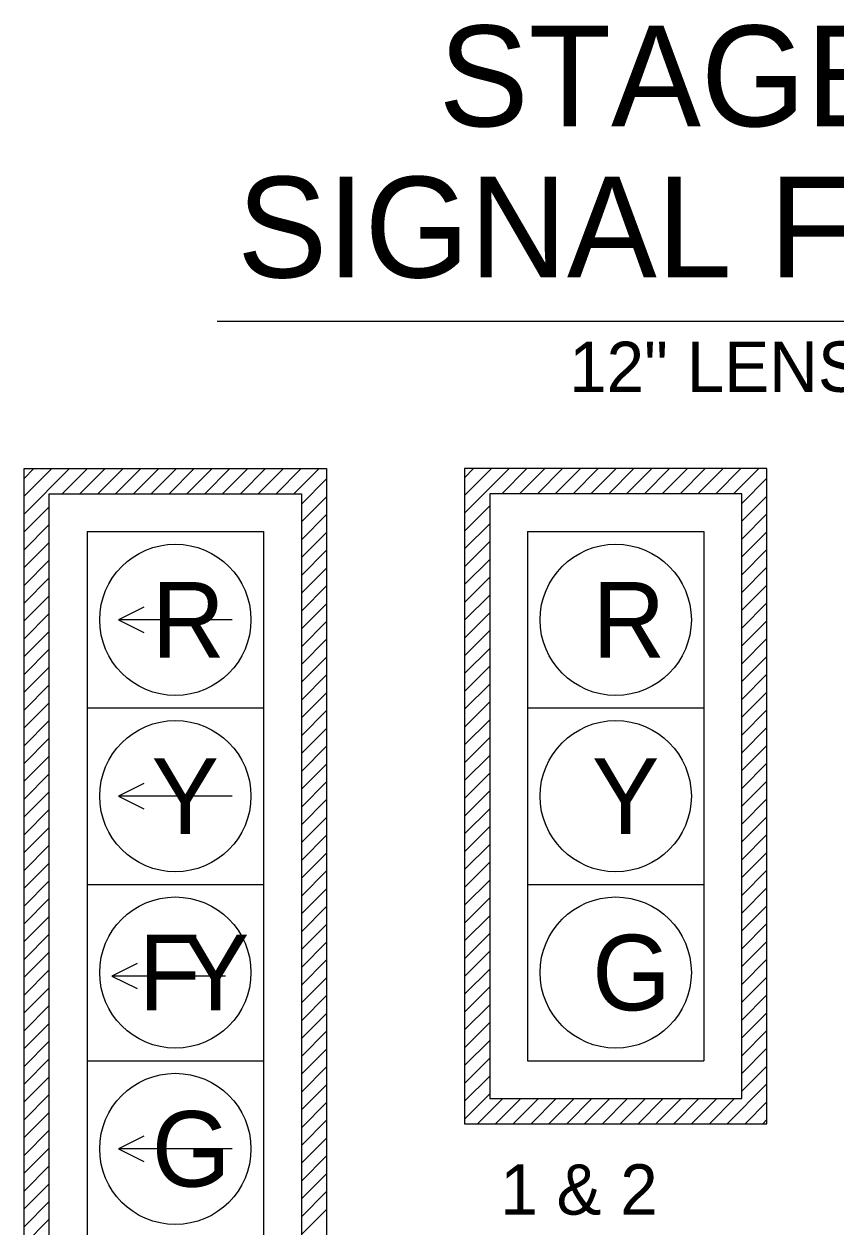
# Model space of a CAD drawing. Extents: x -218554 to 420030, y -565899 to -483460.
# Drawn here: x 419080.6 to 419145, y -565376.2 to -565280.7 of the extents above; entities that cross this region are included whole.
import ezdxf

# ---------------------------------------------------------------- set-up
doc = ezdxf.new("R2010")
doc.units = 0
doc.layers.add('T_Drafting', color=7, linetype='Continuous')
doc.layers.add('T_Notes', color=7, linetype='Continuous')

msp = doc.modelspace()

# ---------------------------------------------------------------- linework, layer by layer
at = {"layer": 'T_Drafting'}
for p, q in [((419080.555, -565381.971), (419080.555, -565315.971)), ((419080.555, -565315.971), (419104.555, -565315.971)), ((419080.555, -565319.578), (419084.163, -565315.971)), ((419080.555, -565318.163), (419082.748, -565315.971)), ((419080.555, -565316.749), (419081.334, -565315.971)), ((419083.577, -565317.971), (419085.577, -565315.971)), ((419084.991, -565317.971), (419086.991, -565315.971)), ((419086.405, -565317.971), (419088.405, -565315.971)), ((419087.819, -565317.971), (419089.819, -565315.971)), ((419089.234, -565317.971), (419091.234, -565315.971)), ((419090.648, -565317.971), (419092.648, -565315.971)), ((419092.062, -565317.971), (419094.062, -565315.971)), ((419093.476, -565317.971), (419095.476, -565315.971)), ((419094.89, -565317.971), (419096.89, -565315.971)), ((419096.305, -565317.971), (419098.305, -565315.971)), ((419097.719, -565317.971), (419099.719, -565315.971)), ((419099.133, -565317.971), (419101.133, -565315.971)), ((419100.547, -565317.971), (419102.547, -565315.971)), ((419101.962, -565317.971), (419103.962, -565315.971)), ((419104.555, -565315.971), (419104.555, -565381.971)), ((419139.493, -565315.971), (419115.493, -565315.971)), ((419115.493, -565315.971), (419115.493, -565367.971)), ((419115.493, -565319.517), (419119.04, -565315.971)), ((419115.493, -565318.103), (419117.626, -565315.971)), ((419115.493, -565316.689), (419116.212, -565315.971)), ((419118.454, -565317.971), (419120.454, -565315.971)), ((419119.869, -565317.971), (419121.869, -565315.971)), ((419121.283, -565317.971), (419123.283, -565315.971)), ((419122.697, -565317.971), (419124.697, -565315.971)), ((419124.111, -565317.971), (419126.111, -565315.971)), ((419125.525, -565317.971), (419127.525, -565315.971)), ((419126.94, -565317.971), (419128.94, -565315.971)), ((419128.354, -565317.971), (419130.354, -565315.971)), ((419129.768, -565317.971), (419131.768, -565315.971)), ((419131.182, -565317.971), (419133.182, -565315.971)), ((419132.596, -565317.971), (419134.596, -565315.971)), ((419134.011, -565317.971), (419136.011, -565315.971)), ((419135.425, -565317.971), (419137.425, -565315.971)), ((419136.839, -565317.971), (419138.839, -565315.971)), ((419139.493, -565367.971), (419139.493, -565315.971)), ((419102.555, -565318.791), (419104.555, -565316.791)), ((419137.493, -565318.731), (419139.493, -565316.731)), ((419102.555, -565320.205), (419104.555, -565318.205)), ((419137.493, -565320.145), (419139.493, -565318.145)), ((419080.555, -565320.992), (419082.555, -565318.992)), ((419102.555, -565321.619), (419104.555, -565319.619)), ((419115.493, -565320.932), (419117.493, -565318.932)), ((419137.493, -565321.559), (419139.493, -565319.559)), ((419080.555, -565322.406), (419082.555, -565320.406)), ((419115.493, -565322.346), (419117.493, -565320.346)), ((419085.555, -565320.971), (419099.555, -565320.971)), ((419085.555, -565320.971), (419085.555, -565334.971)), ((419099.555, -565320.971), (419099.555, -565334.971)), ((419102.555, -565323.033), (419104.555, -565321.033)), ((419115.493, -565323.76), (419117.493, -565321.76)), ((419120.493, -565320.971), (419134.493, -565320.971)), ((419120.493, -565320.971), (419120.493, -565334.971)), ((419134.493, -565320.971), (419134.493, -565334.971)), ((419137.493, -565322.973), (419139.493, -565320.973)), ((419080.555, -565323.82), (419082.555, -565321.82)), ((419102.555, -565324.448), (419104.555, -565322.448)), ((419137.493, -565324.387), (419139.493, -565322.387)), ((419080.555, -565325.234), (419082.555, -565323.234)), ((419115.493, -565325.174), (419117.493, -565323.174)), ((419080.555, -565326.649), (419082.555, -565324.649)), ((419102.555, -565325.862), (419104.555, -565323.862)), ((419115.493, -565326.588), (419117.493, -565324.588)), ((419137.493, -565325.802), (419139.493, -565323.802)), ((419102.555, -565327.276), (419104.555, -565325.276)), ((419137.493, -565327.216), (419139.493, -565325.216)), ((419080.555, -565328.063), (419082.555, -565326.063)), ((419115.493, -565328.003), (419117.493, -565326.003)), ((419080.555, -565329.477), (419082.555, -565327.477)), ((419102.555, -565328.69), (419104.555, -565326.69)), ((419115.493, -565329.417), (419117.493, -565327.417)), ((419137.493, -565328.63), (419139.493, -565326.63)), ((419097.055, -565327.971), (419088.055, -565327.971)), ((419102.555, -565330.105), (419104.555, -565328.105)), ((419137.493, -565330.044), (419139.493, -565328.044)), ((419080.555, -565330.891), (419082.555, -565328.891)), ((419115.493, -565330.831), (419117.493, -565328.831)), ((419080.555, -565332.306), (419082.555, -565330.306)), ((419102.555, -565331.519), (419104.555, -565329.519)), ((419115.493, -565332.245), (419117.493, -565330.245)), ((419137.493, -565331.458), (419139.493, -565329.458)), ((419102.555, -565332.933), (419104.555, -565330.933)), ((419137.493, -565332.873), (419139.493, -565330.873)), ((419080.555, -565333.72), (419082.555, -565331.72)), ((419115.493, -565333.659), (419117.493, -565331.659)), ((419137.493, -565334.287), (419139.493, -565332.287)), ((419080.555, -565335.134), (419082.555, -565333.134)), ((419102.555, -565334.347), (419104.555, -565332.347)), ((419115.493, -565335.074), (419117.493, -565333.074)), ((419102.555, -565335.761), (419104.555, -565333.761)), ((419137.493, -565335.701), (419139.493, -565333.701)), ((419080.555, -565336.548), (419082.555, -565334.548)), ((419085.555, -565334.971), (419099.555, -565334.971)), ((419085.555, -565334.971), (419085.555, -565348.971)), ((419099.555, -565334.971), (419099.555, -565348.971)), ((419115.493, -565336.488), (419117.493, -565334.488)), ((419120.493, -565334.971), (419134.493, -565334.971)), ((419120.493, -565334.971), (419120.493, -565348.971)), ((419134.493, -565334.971), (419134.493, -565348.971)), ((419137.493, -565337.115), (419139.493, -565335.115)), ((419080.555, -565337.962), (419082.555, -565335.962)), ((419102.555, -565337.176), (419104.555, -565335.176)), ((419115.493, -565337.902), (419117.493, -565335.902)), ((419102.555, -565338.59), (419104.555, -565336.59)), ((419137.493, -565338.53), (419139.493, -565336.53)), ((419080.555, -565339.377), (419082.555, -565337.377)), ((419102.555, -565340.004), (419104.555, -565338.004)), ((419115.493, -565339.316), (419117.493, -565337.316)), ((419137.493, -565339.944), (419139.493, -565337.944)), ((419080.555, -565340.791), (419082.555, -565338.791)), ((419115.493, -565340.731), (419117.493, -565338.731)), ((419102.555, -565341.418), (419104.555, -565339.418)), ((419137.493, -565341.358), (419139.493, -565339.358)), ((419080.555, -565342.205), (419082.555, -565340.205)), ((419102.555, -565342.832), (419104.555, -565340.832)), ((419115.493, -565342.145), (419117.493, -565340.145)), ((419137.493, -565342.772), (419139.493, -565340.772)), ((419080.555, -565343.619), (419082.555, -565341.619)), ((419115.493, -565343.559), (419117.493, -565341.559)), ((419097.055, -565341.971), (419088.055, -565341.971)), ((419102.555, -565344.247), (419104.555, -565342.247)), ((419137.493, -565344.186), (419139.493, -565342.186)), ((419080.555, -565345.033), (419082.555, -565343.033)), ((419102.555, -565345.661), (419104.555, -565343.661)), ((419115.493, -565344.973), (419117.493, -565342.973)), ((419137.493, -565345.601), (419139.493, -565343.601)), ((419080.555, -565346.448), (419082.555, -565344.448)), ((419115.493, -565346.387), (419117.493, -565344.387)), ((419102.555, -565347.075), (419104.555, -565345.075)), ((419137.493, -565347.015), (419139.493, -565345.015)), ((419080.555, -565347.862), (419082.555, -565345.862)), ((419102.555, -565348.489), (419104.555, -565346.489)), ((419115.493, -565347.802), (419117.493, -565345.802)), ((419137.493, -565348.429), (419139.493, -565346.429)), ((419080.555, -565349.276), (419082.555, -565347.276)), ((419115.493, -565349.216), (419117.493, -565347.216)), ((419102.555, -565349.904), (419104.555, -565347.904)), ((419137.493, -565349.843), (419139.493, -565347.843)), ((419080.555, -565350.69), (419082.555, -565348.69)), ((419085.555, -565348.971), (419099.555, -565348.971)), ((419085.555, -565348.971), (419085.555, -565362.971)), ((419099.555, -565348.971), (419099.555, -565362.971)), ((419102.555, -565351.318), (419104.555, -565349.318)), ((419115.493, -565350.63), (419117.493, -565348.63)), ((419120.493, -565348.971), (419134.493, -565348.971)), ((419120.493, -565348.971), (419120.493, -565362.971)), ((419134.493, -565348.971), (419134.493, -565362.971)), ((419137.493, -565351.257), (419139.493, -565349.257)), ((419080.555, -565352.105), (419082.555, -565350.105)), ((419115.493, -565352.044), (419117.493, -565350.044)), ((419102.555, -565352.732), (419104.555, -565350.732)), ((419137.493, -565352.672), (419139.493, -565350.672)), ((419080.555, -565353.519), (419082.555, -565351.519)), ((419102.555, -565354.146), (419104.555, -565352.146)), ((419115.493, -565353.458), (419117.493, -565351.458)), ((419137.493, -565354.086), (419139.493, -565352.086)), ((419080.555, -565354.933), (419082.555, -565352.933)), ((419115.493, -565354.873), (419117.493, -565352.873)), ((419102.555, -565355.56), (419104.555, -565353.56)), ((419137.493, -565355.5), (419139.493, -565353.5)), ((419080.555, -565356.347), (419082.555, -565354.347)), ((419102.555, -565356.975), (419104.555, -565354.975)), ((419115.493, -565356.287), (419117.493, -565354.287)), ((419137.493, -565356.914), (419139.493, -565354.914)), ((419080.555, -565357.761), (419082.555, -565355.761)), ((419115.493, -565357.701), (419117.493, -565355.701)), ((419096.53, -565356.248), (419087.53, -565356.248)), ((419102.555, -565358.389), (419104.555, -565356.389)), ((419115.493, -565359.115), (419117.493, -565357.115)), ((419137.493, -565358.328), (419139.493, -565356.328)), ((419080.555, -565359.176), (419082.555, -565357.176)), ((419102.555, -565359.803), (419104.555, -565357.803)), ((419137.493, -565359.743), (419139.493, -565357.743)), ((419080.555, -565360.59), (419082.555, -565358.59)), ((419115.493, -565360.53), (419117.493, -565358.53)), ((419102.555, -565361.217), (419104.555, -565359.217)), ((419115.493, -565361.944), (419117.493, -565359.944)), ((419137.493, -565361.157), (419139.493, -565359.157)), ((419080.555, -565362.004), (419082.555, -565360.004)), ((419102.555, -565362.631), (419104.555, -565360.631)), ((419137.493, -565362.571), (419139.493, -565360.571)), ((419080.555, -565363.418), (419082.555, -565361.418)), ((419115.493, -565363.358), (419117.493, -565361.358)), ((419080.555, -565364.832), (419082.555, -565362.832)), ((419102.555, -565364.046), (419104.555, -565362.046)), ((419115.493, -565364.772), (419117.493, -565362.772)), ((419137.493, -565363.985), (419139.493, -565361.985)), ((419085.555, -565362.971), (419099.555, -565362.971)), ((419085.555, -565362.971), (419085.555, -565376.971)), ((419099.555, -565362.971), (419099.555, -565376.971)), ((419102.555, -565365.46), (419104.555, -565363.46)), ((419120.493, -565362.971), (419134.493, -565362.971)), ((419137.493, -565365.4), (419139.493, -565363.4)), ((419080.555, -565366.247), (419082.555, -565364.247)), ((419115.493, -565366.186), (419117.493, -565364.186)), ((419080.555, -565367.661), (419082.555, -565365.661)), ((419102.555, -565366.874), (419104.555, -565364.874)), ((419115.493, -565367.601), (419117.493, -565365.601)), ((419136.337, -565367.971), (419139.493, -565364.814)), ((419102.555, -565368.288), (419104.555, -565366.288)), ((419116.538, -565367.971), (419118.538, -565365.971)), ((419117.952, -565367.971), (419119.952, -565365.971)), ((419119.366, -565367.971), (419121.366, -565365.971)), ((419120.78, -565367.971), (419122.78, -565365.971)), ((419122.194, -565367.971), (419124.194, -565365.971)), ((419123.609, -565367.971), (419125.609, -565365.971)), ((419125.023, -565367.971), (419127.023, -565365.971)), ((419126.437, -565367.971), (419128.437, -565365.971)), ((419127.851, -565367.971), (419129.851, -565365.971)), ((419129.266, -565367.971), (419131.266, -565365.971)), ((419130.68, -565367.971), (419132.68, -565365.971)), ((419132.094, -565367.971), (419134.094, -565365.971)), ((419133.508, -565367.971), (419135.508, -565365.971)), ((419134.922, -565367.971), (419136.922, -565365.971)), ((419137.751, -565367.971), (419139.493, -565366.228)), ((419080.555, -565369.075), (419082.555, -565367.075)), ((419080.555, -565370.489), (419082.555, -565368.489)), ((419102.555, -565369.703), (419104.555, -565367.703)), ((419115.493, -565367.971), (419139.493, -565367.971)), ((419139.165, -565367.971), (419139.493, -565367.642)), ((419102.555, -565371.117), (419104.555, -565369.117)), ((419080.555, -565371.904), (419082.555, -565369.904)), ((419097.055, -565369.971), (419088.055, -565369.971)), ((419080.555, -565373.318), (419082.555, -565371.318)), ((419102.555, -565372.531), (419104.555, -565370.531)), ((419102.555, -565373.945), (419104.555, -565371.945)), ((419080.555, -565374.732), (419082.555, -565372.732)), ((419080.555, -565376.146), (419082.555, -565374.146)), ((419102.555, -565375.359), (419104.555, -565373.359)), ((419102.555, -565376.774), (419104.555, -565374.774)), ((419080.555, -565377.56), (419082.555, -565375.56))]:
    msp.add_line(p, q, dxfattribs=at)
for points in [[(419082.555, -565379.971), (419082.555, -565317.971), (419102.555, -565317.971), (419102.555, -565379.971)], [(419137.493, -565365.971), (419137.493, -565317.971), (419117.493, -565317.971), (419117.493, -565365.971)]]:
    msp.add_lwpolyline(points, close=True, dxfattribs=at)
for points in [[(419090.055, -565326.971), (419088.055, -565327.971), (419090.055, -565328.971)], [(419090.055, -565340.971), (419088.055, -565341.971), (419090.055, -565342.971)], [(419089.53, -565355.248), (419087.53, -565356.248), (419089.53, -565357.248)], [(419090.055, -565368.971), (419088.055, -565369.971), (419090.055, -565370.971)]]:
    msp.add_lwpolyline(points, dxfattribs=at)
for centre in [(419092.555, -565327.971), (419127.493, -565327.971), (419092.555, -565341.971), (419127.493, -565341.971), (419092.555, -565355.971), (419127.493, -565355.971), (419092.555, -565369.971)]:
    msp.add_circle(centre, 6, dxfattribs=at)
at = {"layer": 'T_Notes'}
msp.add_line((419095.87, -565304.265), (419194.055, -565304.265), dxfattribs=at)

# ---------------------------------------------------------------- texts
at = {"layer": 'T_Drafting'}
msp.add_text('12" LENSES', height=4, rotation=0.07203, dxfattribs=at).set_placement((419123.796, -565309.899))
for s, p in [('R', (419090.69, -565330.969)), ('R', (419125.628, -565330.969)), ('Y', (419090.667, -565344.969)), ('Y', (419125.604, -565344.969)), ('F', (419089.65, -565358.969)), ('Y', (419093.075, -565358.969)), ('G', (419125.627, -565358.969)), ('G', (419090.689, -565372.969))]:
    msp.add_text(s, height=5.998, dxfattribs=at).set_placement(p)
at = {"layer": 'T_Notes'}
for s, p in [('STAGE 4B', (419113.451, -565288.796)), ('SIGNAL FACES', (419097.468, -565300.796))]:
    msp.add_text(s, height=8, rotation=360, dxfattribs=at).set_placement(p)
msp.add_text('1 & 2', height=4, dxfattribs=at).set_placement((419118.337, -565375.192))

doc.saveas('drawing.dxf')
